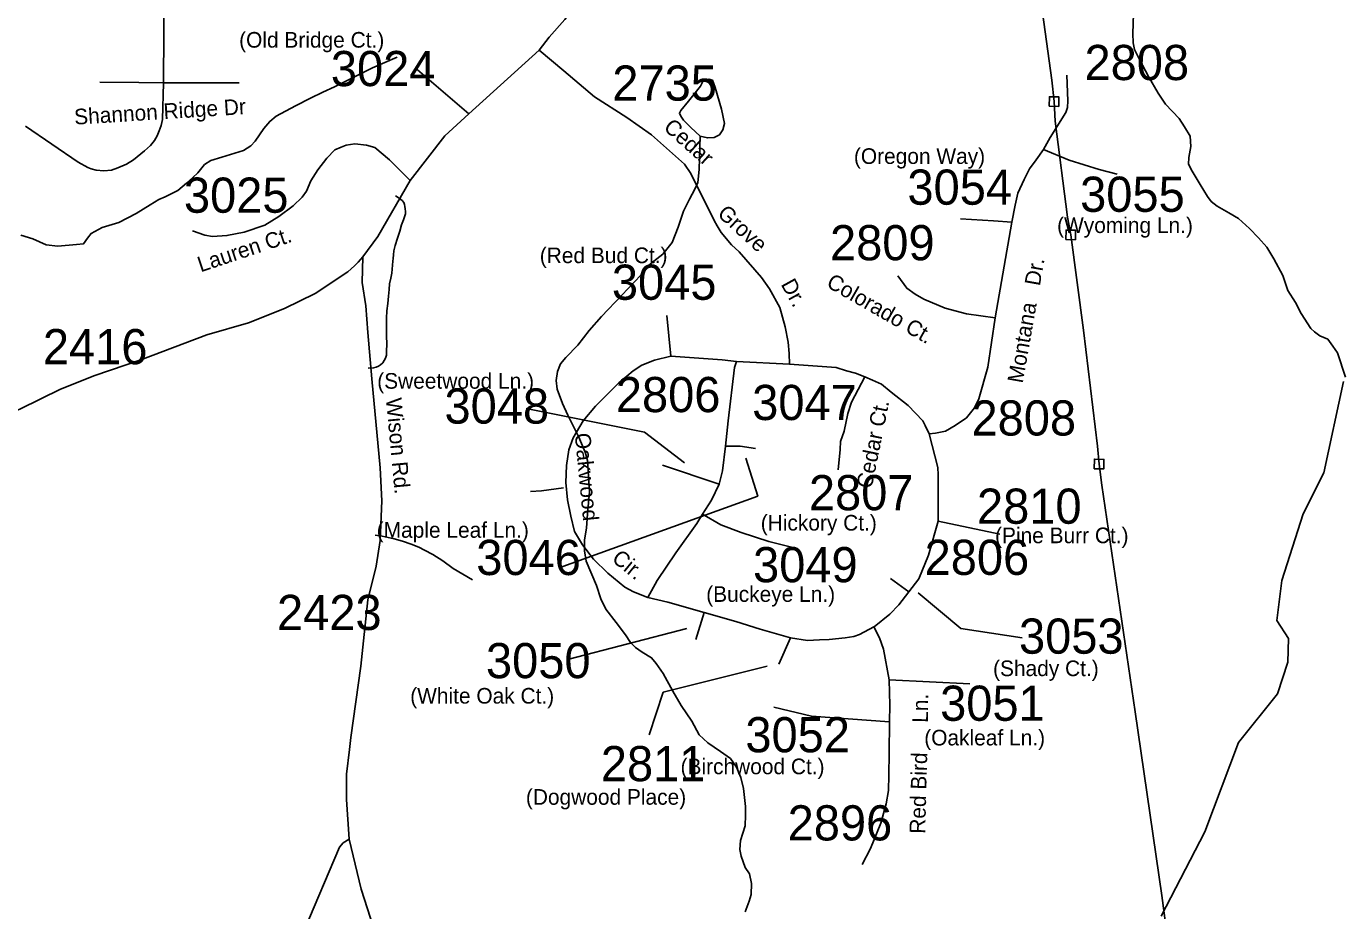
# Model space of a CAD drawing. Extents: x 1268485 to 1426702, y 514839 to 616766.
# Drawn here: x 1347749 to 1353261, y 524068 to 527780 of the extents above; entities that cross this region are included whole.
import ezdxf

# ---------------------------------------------------------------- set-up
doc = ezdxf.new("R2010")
doc.units = 0
for name, color, linetype in [('Old_Level_10', 7, 'Continuous'), ('Old_Level_11', 7, 'Continuous'), ('Old_Level_32', 7, 'Continuous'), ('Old_Level_35', 7, 'Continuous'), ('Old_Level_56', 7, 'Continuous'), ('Old_Level_59', 7, 'Continuous'), ('Old_Level_62', 7, 'Continuous'), ('Old_Level_8', 7, 'Continuous')]:
    doc.layers.add(name, color=color, linetype=linetype)

msp = doc.modelspace()

# ---------------------------------------------------------------- linework, layer by layer
at = {"layer": 'Old_Level_11'}
msp.add_line((1350027.498, 525123.934), (1350523.244, 525252.915), dxfattribs=at)
for points in [[(1349849.03, 526175.621), (1350344.776, 526076.406), (1350513.33, 525947.425)], [(1349986.813, 525506.865), (1350820.692, 525808.523), (1350771.118, 525967.268)], [(1351931.164, 525213.228), (1351673.376, 525252.915), (1351494.907, 525401.738)], [(1350364.605, 524806.444), (1350424.095, 524985.032), (1350860.352, 525094.169)]]:
    msp.add_lwpolyline(points, dxfattribs=at)
at = {"layer": 'Old_Level_32'}
for p, q in [((1349903.465, 527679.602), (1349608.1, 527412.211)), ((1349608.1, 527412.211), (1349391.562, 527597.373)), ((1351817.533, 526555.818), (1351888.566, 526958.285)), ((1350456.565, 526395.933), (1350438.571, 526565.926)), ((1350953.788, 526361.937), (1350732.17, 526372.961)), ((1350659.243, 525858.391), (1350421.524, 525938.333)), ((1351579.185, 525702.833), (1351837.394, 525647.883)), ((1351455.889, 525405.945), (1351377.947, 525461.656)), ((1350596.026, 525319.242), (1350560.984, 525206.68)), ((1350958.526, 525213.342), (1350909.277, 525103.077)), ((1351372.893, 525036.479), (1351710.99, 525020.837))]:
    msp.add_line(p, q, dxfattribs=at)
for points in [[(1350101.407, 527935.975), (1350075.835, 527893.707), (1350044.581, 527848.682), (1350011.433, 527808.251), (1349945.137, 527733.822), (1349903.465, 527679.602)], [(1349903.465, 527679.602), (1350006.698, 527592.309), (1350135.028, 527483.423), (1350271.409, 527397.049), (1350374.642, 527324.458), (1350512.916, 527201.328), (1350539.434, 527161.817), (1350637.932, 526964.258), (1350650.245, 526942.205), (1350666.819, 526914.18), (1350710.385, 526862.723), (1350742.585, 526833.319), (1350836.822, 526725.351), (1350869.97, 526678.489), (1350913.536, 526599.466), (1350936.741, 526519.064), (1350948.106, 526453.824), (1350952.842, 526406.961), (1350953.788, 526361.937)], [(1352020.212, 527262.433), (1352048.625, 527312.971), (1352114.608, 527418.726), (1352121.012, 527438.606), (1352123.576, 527466.568), (1352118.656, 527574.466)], [(1349608.1, 527412.211), (1349507.106, 527320.781), (1349361.254, 527132.421)], [(1349361.254, 527132.421), (1349274.122, 527218.795), (1349213.599, 527270.775), (1349178.7, 527280.961), (1349129.259, 527286.782), (1349092.906, 527280.961), (1349071.443, 527273.009), (1349044.925, 527261.064), (1349010.829, 527226.147), (1348973.419, 527176.987), (1348944.533, 527131.502), (1348925.591, 527088.315), (1348907.596, 527062.586), (1348870.66, 527026.75), (1348809.573, 526982.185), (1348751.8, 526945.43), (1348663.72, 526916.025), (1348592.215, 526901.782), (1348531.601, 526898.107), (1348499.4, 526902.702), (1348447.309, 526921.079)], [(1351888.566, 526958.285), (1351902.299, 527029.498), (1351912.717, 527080.036), (1351939.236, 527137.006), (1351961.966, 527182.031), (1351989.432, 527218.786), (1352020.212, 527262.433)], [(1352020.212, 527262.433), (1352128.655, 527217.867), (1352254.617, 527179.274), (1352330.385, 527159.059)], [(1349361.254, 527132.421), (1349225.821, 526897.181), (1349162.365, 526812.644)], [(1351888.566, 526958.285), (1351810.904, 526962.879), (1351671.682, 526972.068)], [(1349162.365, 526812.644), (1349143.423, 526790.591), (1349128.27, 526774.971), (1349099.857, 526749.242), (1348962.531, 526658.274), (1348833.726, 526595.79), (1348682.192, 526535.144), (1348508.225, 526484.401), (1348230.429, 526379.855), (1348037.222, 526313.696), (1347893.264, 526256.726), (1347725.629, 526174.946), (1347471.809, 526062.843), (1346646.883, 525715.122), (1345965.279, 525407.42), (1345766.546, 525394.253), (1345355.424, 525420.241), (1345286.239, 525399.728), (1345224.229, 525345.881), (1345101.233, 525240.749), (1345044.859, 525176.645), (1344623.712, 524712.006)], [(1349105.065, 524367.979), (1349093.7, 524535.215), (1349093.7, 524641.805), (1349105.993, 524743.984), (1349111.809, 524794.915), (1349153.98, 525094.684), (1349183.062, 525372.335), (1349217.962, 525513.488), (1349234.818, 525622.248), (1349242.682, 525788.519), (1349235.411, 525926.762), (1349200.721, 526300.38), (1349183.675, 526495.173), (1349175.152, 526606.357), (1349160.471, 526705.136), (1349162.365, 526812.644)], [(1351817.533, 526555.818), (1351698.199, 526573.276), (1351608.226, 526597.167), (1351518.726, 526634.382), (1351481.79, 526655.516), (1351446.747, 526680.326), (1351408.863, 526732.702)], [(1351540.509, 526069.273), (1351567.975, 526072.949), (1351608.699, 526081.219), (1351649.33, 526104.258), (1351698.018, 526137.295), (1351731.348, 526178.16), (1351749.083, 526216.941), (1351786.929, 526349.407), (1351817.533, 526555.818)], [(1350456.565, 526395.933), (1350386.955, 526378.016), (1350333.918, 526357.8), (1350297.928, 526333.909), (1350271.41, 526310.938), (1350237.315, 526283.371), (1350139.764, 526185.052), (1350087.674, 526123.487), (1350046.476, 526052.274), (1350027.06, 526002.195), (1350018.537, 525936.036), (1350014.749, 525865.283), (1350022.325, 525792.692), (1350035.585, 525723.776), (1350052.158, 525658.995), (1350085.307, 525602.945), (1350131.715, 525544.136), (1350191.381, 525484.41), (1350262.886, 525426.061), (1350299.823, 525405.845), (1350359.49, 525382.874)], [(1350732.17, 526372.961), (1350671.557, 526380.312), (1350456.565, 526395.933)], [(1350732.17, 526372.961), (1350723.647, 526347.233), (1350696.654, 526123.486), (1350685.289, 526017.816)], [(1351270.115, 526308.64), (1351231.954, 526323.559), (1351194.158, 526334.525), (1351150.783, 526347.234), (1350953.788, 526361.937)], [(1351270.115, 526308.64), (1351214.71, 526202.51), (1351198.61, 526154.729), (1351183.456, 526080.3), (1351168.303, 526037.113), (1351166.409, 526004.033), (1351158.359, 525918.119)], [(1351540.509, 526069.273), (1351524.409, 526104.19), (1351513.653, 526123.397), (1351452.571, 526188.083), (1351381.822, 526244.64), (1351340.2, 526278.318), (1351302.316, 526294.858), (1351270.115, 526308.64)], [(1351579.185, 525702.833), (1351578.741, 525897.78), (1351577.345, 525927.822), (1351540.509, 526069.273)], [(1350685.289, 526017.816), (1350673.45, 525914.442), (1350659.243, 525858.391)], [(1350685.289, 526017.816), (1350747.797, 526017.816), (1350811.252, 526007.708)], [(1350659.243, 525858.391), (1350626.095, 525791.313), (1350588.685, 525732.965)], [(1350588.685, 525732.965), (1350565.046, 525693.546), (1350476.93, 525569.405), (1350399.268, 525453.627), (1350359.49, 525382.874)], [(1350588.685, 525732.965), (1350666.347, 525687.94), (1350750.638, 525655.78), (1350867.13, 525617.187), (1350968.942, 525591.918)], [(1351455.889, 525405.945), (1351497.447, 525460.41), (1351538.263, 525560.673), (1351579.185, 525702.833)], [(1351308.003, 525259.285), (1351309.758, 525260.152), (1351375.004, 525312.555), (1351412.822, 525351.226), (1351455.889, 525405.945)], [(1350359.49, 525382.874), (1350443.781, 525363.577), (1350596.026, 525319.242)], [(1350596.026, 525319.242), (1350728.383, 525281.339), (1350831.616, 525249.178), (1350958.526, 525213.342)], [(1350958.526, 525213.342), (1351029.558, 525202.315), (1351080.701, 525205.072), (1351120.479, 525205.991), (1351187.593, 525213.922), (1351224.561, 525219.55), (1351247.879, 525226.716), (1351308.003, 525259.285)], [(1351308.003, 525259.285), (1351331.681, 525213.341), (1351349.202, 525165.101), (1351372.893, 525036.479)], [(1351372.893, 525036.479), (1351375.246, 524931.248), (1351374.3, 524860.494)], [(1351374.3, 524860.494), (1351046.132, 524883.925), (1350888.441, 524922.978)], [(1351374.3, 524860.494), (1351372.405, 524729.096), (1351371.932, 524636.749), (1351370.216, 524573.05), (1351359.684, 524516.542), (1351337.727, 524434.952), (1351293.796, 524329.385), (1351258.754, 524262.307)], [(1349105.065, 524367.979), (1349080.44, 524353.277), (1349065.286, 524334.899), (1348915.363, 523981.746)], [(1349862.272, 522009.451), (1349824.73, 522122.46), (1349572.702, 522887.349), (1349310.782, 523676.541), (1349155.206, 524158.101), (1349105.065, 524367.979)]]:
    msp.add_lwpolyline(points, dxfattribs=at)
at = {"layer": 'Old_Level_35'}
msp.add_line((1348325.101, 527542.827), (1348643.342, 527542.211), dxfattribs=at)
for points in [[(1348328.279, 527952.572), (1348327.664, 527753.262), (1348325.101, 527542.827)], [(1348325.101, 527542.827), (1348222.37, 527543.647), (1348058.123, 527545.8)], [(1348325.101, 527542.827), (1348320.795, 527388.32), (1348315.156, 527363.304), (1348307.261, 527341.107), (1348299.367, 527320.397), (1348287.269, 527301.07), (1348271.48, 527279.642), (1348246.361, 527257.446), (1348199.916, 527219.511), (1348170.594, 527200.954), (1348134.095, 527185.165), (1348107.951, 527175.733), (1348074.527, 527173.015), (1348042.642, 527176.245), (1348022.341, 527181.73), (1348008.603, 527187.831), (1347968.003, 527209.822), (1347746.546, 527360.382)], [(1349299.713, 527068.695), (1349315.092, 527058.75), (1349327.6, 527048.754), (1349334.982, 527040.141), (1349338.263, 527032.196), (1349339.596, 527022.866), (1349341.031, 527013.639), (1349342.262, 527002.976), (1349341.646, 526992.364), (1349333.034, 526967.81), (1349325.652, 526946.587), (1349318.373, 526919.981), (1349308.325, 526890.198), (1349297.868, 526859.645), (1349293.152, 526837.755), (1349291.101, 526820.48), (1349289.871, 526805.869), (1349289.153, 526793.926), (1349287.923, 526777.982), (1349283.924, 526743.483), (1349279.926, 526722.311), (1349275.21, 526699.089), (1349272.646, 526675.2), (1349269.981, 526646.647), (1349267.213, 526616.145), (1349264.034, 526585.541), (1349261.984, 526555.04), (1349261.369, 526508.646), (1349261.984, 526482.041), (1349263.214, 526444.26), (1349262.599, 526417.706), (1349261.369, 526399.815), (1349257.985, 526386.487), (1349252.756, 526376.542), (1349245.99, 526367.93), (1349237.377, 526359.318), (1349228.765, 526353.32), (1349218.923, 526348.706), (1349207.645, 526346.04), (1349184.372, 526345.374)], [(1350005.092, 525842.74), (1349913.024, 525829.616), (1349866.272, 525827.002)], [(1349214.207, 525644.609), (1349243.529, 525639.431), (1349294.484, 525629.383), (1349329.651, 525618.772), (1349365.535, 525606.11), (1349398.036, 525593.551), (1349421.924, 525581.606), (1349456.373, 525562.383), (1349498.204, 525535.829), (1349542.598, 525503.943), (1349623.593, 525456.166)]]:
    msp.add_lwpolyline(points, dxfattribs=at)
at = {"layer": 'Old_Level_56'}
for points in [[(1351698.395, 530149.401), (1351745.146, 529818.103), (1351774.598, 529611.411), (1351776.545, 529519.328), (1351783.257, 529455.162), (1351840.842, 529075.623), (1351943.222, 528367.025), (1352055.508, 527554.179), (1352065.496, 527463.935), (1352069.645, 527381.812), (1352120.946, 526978.388), (1352135.256, 526904.065), (1352188.438, 526504.604), (1352247.852, 526017.177), (1352254.158, 525942.814), (1352266.185, 525854.53), (1352405.294, 524903.079), (1352518.426, 524132.236), (1352583.394, 523632.491)], [(1352045.093, 527444.336), (1352085.095, 527443.531), (1352085.9, 527483.534), (1352045.897, 527484.339), (1352045.093, 527444.336)], [(1352114.852, 526884.466), (1352154.855, 526883.66), (1352155.66, 526923.664), (1352115.657, 526924.468), (1352114.852, 526884.466)], [(1352233.754, 525923.215), (1352273.757, 525922.411), (1352274.561, 525962.413), (1352234.559, 525963.219), (1352233.754, 525923.215)]]:
    msp.add_lwpolyline(points, dxfattribs=at)
at = {"layer": 'Old_Level_59'}
msp.add_lwpolyline([(1352515.238, 524045.663), (1352698.247, 524399.737), (1352839.22, 524774.368), (1353003.262, 524977.882), (1353047.245, 525111.576), (1353049.193, 525210.052), (1353001.211, 525286.485), (1353021.204, 525453.448), (1353111.221, 525733.96), (1353198.266, 525906.153), (1353281.21, 526288.575)], dxfattribs=at)
at = {"layer": 'Old_Level_62'}
for points in [[(1353288.714, 526307.741), (1353254.963, 526408.889), (1353235.483, 526437.186), (1353214.158, 526466.303), (1353180.529, 526480.964), (1353158.896, 526496.958), (1353143.21, 526511.261), (1353102.507, 526574.417), (1353079.541, 526620.862), (1353046.63, 526671.56), (1353026.022, 526734.358), (1352987.473, 526803.255), (1352958.56, 526852.211), (1352923.394, 526892.351), (1352886.279, 526931.669), (1352839.117, 526972.782), (1352799.747, 526997.388), (1352750.227, 527024.66), (1352724.698, 527044.858), (1352709.217, 527065.67), (1352678.151, 527116.37), (1352645.446, 527171.17), (1352630.067, 527201.056), (1352630.682, 527228.944), (1352639.602, 527274.721), (1352636.628, 527319.064), (1352613.56, 527358.126), (1352590.184, 527392.216), (1352533.59, 527453.271), (1352502.627, 527499.868), (1352462.027, 527568.766), (1352423.579, 527640.124), (1352402.459, 527682.416), (1352397.23, 527710.406), (1352396, 527749.007), (1352400.716, 527874.448)], [(1347727.066, 526903.372), (1347776.791, 526887.583), (1347832.258, 526862.669), (1347882.086, 526857.543), (1347960.313, 526864.207), (1347990.353, 526866.872), (1348006.962, 526891.171), (1348021.316, 526910.549), (1348067.863, 526935.872), (1348138.503, 526955.814), (1348211.297, 526994.517), (1348270.147, 527031.119), (1348306.646, 527052.547), (1348332.995, 527063.467), (1348385.489, 527090.328), (1348422.193, 527121.599), (1348448.747, 527144.872), (1348469.15, 527164.967), (1348497.96, 527200.492), (1348524.411, 527217.204), (1348570.651, 527230.225), (1348661.284, 527258.727), (1348691.734, 527277.849), (1348710.189, 527297.174), (1348747.406, 527350.59), (1348772.114, 527380.425), (1348798.566, 527402.058), (1348879.562, 527445.581), (1348942.308, 527478.748), (1348994.903, 527503.149), (1349043.501, 527525.962), (1349136.492, 527572.508), (1349203.236, 527604.804), (1349306.275, 527650.326)], [(1350579.648, 527318.602), (1350609.381, 527311.477), (1350637.576, 527313.373), (1350659.721, 527324.395), (1350674.177, 527344.644), (1350680.944, 527372.378), (1350668.128, 527432.56), (1350642.189, 527523.347), (1350630.809, 527553.131), (1350614.917, 527557.54), (1350594.822, 527556.309), (1350580.264, 527528.678), (1350530.846, 527465.676), (1350497.935, 527426.101), (1350491.681, 527414.772), (1350497.423, 527402.315), (1350509.11, 527385.706), (1350540.483, 527355.512), (1350579.648, 527318.602)], [(1350767.989, 524062.734), (1350785.008, 524108.358), (1350793.723, 524136.091), (1350794.748, 524182.023), (1350785.623, 524222.418), (1350768.194, 524249.024), (1350751.174, 524296.955), (1350745.843, 524324.944), (1350748.611, 524363.443), (1350767.989, 524424.6), (1350769.014, 524468.891), (1350769.732, 524505.032), (1350761.427, 524580.696), (1350750.457, 524626.833), (1350731.387, 524669.894), (1350706.166, 524706.495), (1350664.848, 524736.894), (1350611.637, 524772.42), (1350574.317, 524806.817), (1350543.662, 524864.078), (1350498.96, 524928.977), (1350464.307, 524989.57), (1350423.911, 525064.26), (1350394.794, 525105.014), (1350375.314, 525130.03), (1350335.841, 525152.996), (1350308.262, 525173.245), (1350286.732, 525193.392), (1350265.406, 525226.61), (1350226.446, 525277.463), (1350183.693, 525334.108), (1350162.572, 525376.401), (1350144.015, 525433.405), (1350100.032, 525534.393), (1350093.06, 525578.018), (1350094.085, 525623.949), (1350101.262, 525673.879), (1350106.491, 525733.704), (1350114.59, 525826.233), (1350105.363, 525957.723), (1350096.136, 525992.377), (1350069.479, 526055.276), (1350023.547, 526148.114), (1350000.684, 526196.199), (1349978.026, 526257.355), (1349974.745, 526293.547), (1349979.563, 526331.174), (1349992.277, 526362.957), (1350014.935, 526390.383), (1350065.993, 526441.031), (1350113.36, 526502.444), (1350164.726, 526561.345), (1350250.745, 526651.517), (1350330.613, 526735.229), (1350371.726, 526784.493), (1350422.681, 526823.658), (1350461.846, 526872.921), (1350487.17, 526936.437), (1350508.7, 527004.104), (1350533.717, 527053.675), (1350556.683, 527096.685), (1350569.293, 527124.367), (1350574.522, 527178.398), (1350579.648, 527318.602)]]:
    msp.add_lwpolyline(points, dxfattribs=at)

# ---------------------------------------------------------------- texts
at = {"layer": 'Old_Level_10'}
msp.add_text('Shannon Ridge Dr', height=65.61666, rotation=3.546419, dxfattribs=at).set_placement((1347952.628, 527366.772))
at = {"layer": 'Old_Level_11'}
for s, p in [('(Old Bridge Ct.)', (1348643.211, 527690.266)), ('(Oregon Way)', (1351224.705, 527202.244)), ('(Wyoming Ln.)', (1352077.854, 526912.338)), ('(Red Bud Ct.)', (1349905.625, 526785.779)), ('(Sweetwood Ln.)', (1349223.126, 526258.895)), ('(Hickory Ct.)', (1350833.507, 525663.497)), ('(Maple Leaf Ln.)', (1349220.923, 525633.219)), ('(Pine Burr Ct.)', (1351817.37, 525610.504)), ('(Buckeye Ln.)', (1350604.497, 525364.289)), ('(Shady Ct.)', (1351808.97, 525052.54)), ('(White Oak Ct.)', (1349361.558, 524937.292)), ('(Oakleaf Ln.)', (1351520.146, 524761.667)), ('(Birchwood Ct.)', (1350496.786, 524640.928)), ('(Dogwood Place)', (1349847.33, 524512.87))]:
    msp.add_text(s, height=65.61666, dxfattribs=at).set_placement(p)
for s, height, rotation, p in [('Cedar', 65.6167, 318.315703, (1350421.42, 527349.73)), ('Grove', 65.6167, 317.599517, (1350647.349, 526987.985)), ('Lauren Ct.', 65.6167, 18.461036, (1348481.285, 526746.866)), ('Montana   Dr.', 65.61666, 79.990794, (1351933.335, 526279.165)), ('Dr.', 65.6167, 298.868406, (1350916.379, 526697.455)), ('Colorado Ct.', 65.61666, 330.222656, (1351104.948, 526689.144)), ('Wison Rd.', 65.6167, 275.304747, (1349259.457, 526217.391)), ('Cedar Ct.', 65.6167, 78.492164, (1351298.765, 525836.55)), ('Oakwood ', 65.6167, 275.508939, (1350052.38, 526069.942)), ('Cir.', 65.6167, 320.785508, (1350203.867, 525538.492)), ('Ln.', 65.6167, 89.173886, (1351535.096, 524856.233)), ('Red Bird', 65.6167, 88.456983, (1351523.842, 524390.338))]:
    msp.add_text(s, height=height, rotation=rotation, dxfattribs=at).set_placement(p)
at = {"layer": 'Old_Level_8'}
for s, p in [('3024', (1349028.403, 527528.677)), ('2808', (1352193.027, 527554.073)), ('2735', (1350210.233, 527467.692)), ('3054', (1351449.467, 527031.045)), ('3025', (1348411.368, 526997.312)), ('3055', (1352174.622, 527001.168)), ('2809', (1351124.374, 526797.883)), ('3045', (1350208.474, 526631.983)), ('2416', (1347819.118, 526361.719)), ('2806', (1350225.039, 526160.461)), ('3048', (1349505.498, 526112.358)), ('3047', (1350797.588, 526127.32)), ('2808', (1351718.536, 526062.31)), ('2807', (1351035.865, 525748.846)), ('2810', (1351741.578, 525692.058)), ('3046', (1349639.038, 525476.842)), ('2806', (1351521.611, 525477.464)), ('3049', (1350801.269, 525446.578)), ('2423', (1348802.327, 525246.129)), ('3053', (1351918.012, 525146.734)), ('3050', (1349679.731, 525043.892)), ('3051', (1351586.84, 524865.054)), ('3052', (1350768.897, 524732.956)), ('2811', (1350162.056, 524611.656)), ('2896', (1350946.456, 524362.942))]:
    msp.add_text(s, height=147.6375, dxfattribs=at).set_placement(p)

doc.saveas('drawing.dxf')
